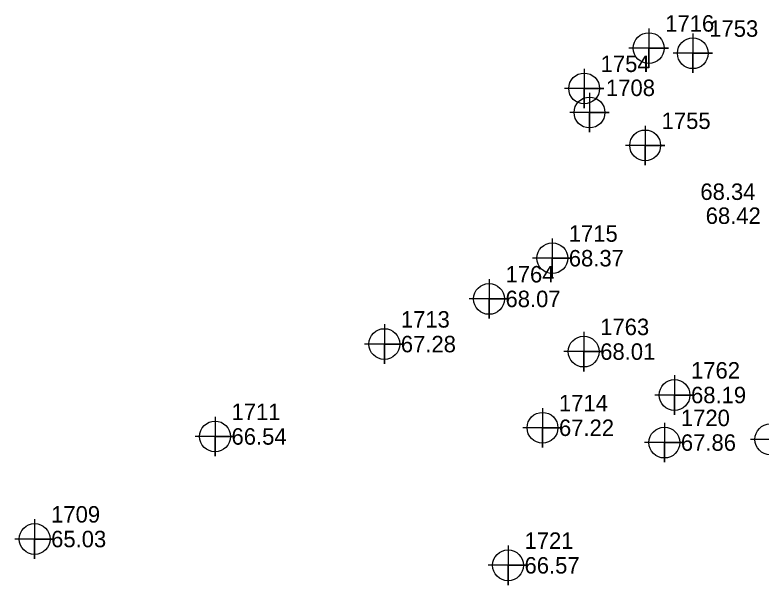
# Model space of a CAD drawing. Extents: x 2062781 to 2066835, y 358981 to 366501.
# Drawn here: x 2066253.4 to 2066366.7, y 366155.4 to 366242 of the extents above; entities that cross this region are included whole.
import ezdxf

# ---------------------------------------------------------------- set-up
doc = ezdxf.new("R2010")
doc.units = 0
for name, color, linetype in [('Exist DTM Regular Point CELL', 7, 'Continuous'), ('Exist DTM Regular Point Cogo Elevation', 7, 'Continuous'), ('Exist DTM Regular Point Cogo Number', 7, 'Continuous')]:
    doc.layers.add(name, color=color, linetype=linetype)

msp = doc.modelspace()

# ---------------------------------------------------------------- linework, layer by layer
at = {"layer": 'Exist DTM Regular Point CELL'}
for points in [[(2066349.68, 366239.93), (2066349.68, 366233.93), (2066349.68, 366236.93), (2066352.68, 366236.93), (2066346.68, 366236.93)], [(2066356.37, 366239.15), (2066356.37, 366233.15), (2066356.37, 366236.15), (2066359.37, 366236.15), (2066353.37, 366236.15)], [(2066339.88, 366233.8), (2066339.88, 366227.8), (2066339.88, 366230.8), (2066342.88, 366230.8), (2066336.88, 366230.8)], [(2066340.69, 366230.15), (2066340.69, 366224.15), (2066340.69, 366227.15), (2066343.69, 366227.15), (2066337.69, 366227.15)], [(2066349.14, 366225.15), (2066349.14, 366219.15), (2066349.14, 366222.15), (2066352.14, 366222.15), (2066346.14, 366222.15)], [(2066335.04, 366208.02), (2066335.04, 366202.02), (2066335.04, 366205.02), (2066338.04, 366205.02), (2066332.04, 366205.02)], [(2066325.43, 366201.84), (2066325.43, 366195.84), (2066325.43, 366198.84), (2066328.43, 366198.84), (2066322.43, 366198.84)], [(2066309.54, 366194.98), (2066309.54, 366188.98), (2066309.54, 366191.98), (2066312.54, 366191.98), (2066306.54, 366191.98)], [(2066339.81, 366193.84), (2066339.81, 366187.84), (2066339.81, 366190.84), (2066342.81, 366190.84), (2066336.81, 366190.84)], [(2066353.6, 366187.24), (2066353.6, 366181.24), (2066353.6, 366184.24), (2066356.6, 366184.24), (2066350.6, 366184.24)], [(2066333.55, 366182.27), (2066333.55, 366176.27), (2066333.55, 366179.27), (2066336.55, 366179.27), (2066330.55, 366179.27)], [(2066283.83, 366180.95), (2066283.83, 366174.95), (2066283.83, 366177.95), (2066286.83, 366177.95), (2066280.83, 366177.95)], [(2066352.06, 366180.02), (2066352.06, 366174.02), (2066352.06, 366177.02), (2066355.06, 366177.02), (2066349.06, 366177.02)], [(2066368.13, 366180.51), (2066368.13, 366174.51), (2066368.13, 366177.51), (2066371.13, 366177.51), (2066365.13, 366177.51)], [(2066256.44, 366165.37), (2066256.44, 366159.37), (2066256.44, 366162.37), (2066259.44, 366162.37), (2066253.44, 366162.37)], [(2066328.32, 366161.38), (2066328.32, 366155.38), (2066328.32, 366158.38), (2066331.32, 366158.38), (2066325.32, 366158.38)]]:
    msp.add_lwpolyline(points, dxfattribs=at)
for centre in [(2066349.68, 366236.93), (2066356.37, 366236.15), (2066339.88, 366230.8), (2066340.69, 366227.15), (2066349.14, 366222.15), (2066335.04, 366205.02), (2066325.43, 366198.84), (2066309.54, 366191.98), (2066339.81, 366190.84), (2066353.6, 366184.24), (2066333.55, 366179.27), (2066283.83, 366177.95), (2066352.06, 366177.02), (2066368.13, 366177.51), (2066256.44, 366162.37), (2066328.32, 366158.38)]:
    msp.add_circle(centre, 2.34, dxfattribs=at)

# ---------------------------------------------------------------- texts
at = {"layer": 'Exist DTM Regular Point Cogo Elevation'}
for s, p in [('68.34', (2066357.52, 366213.87)), ('68.42', (2066358.33, 366210.23)), ('68.37', (2066337.54, 366203.77)), ('68.07', (2066327.93, 366197.59)), ('67.28', (2066312.04, 366190.73)), ('68.01', (2066342.31, 366189.59)), ('68.19', (2066356.1, 366182.99)), ('67.22', (2066336.05, 366178.02)), ('66.54', (2066286.33, 366176.7)), ('67.86', (2066354.56, 366175.77)), ('65.03', (2066258.94, 366161.12)), ('66.57', (2066330.82, 366157.13))]:
    msp.add_text(s, height=2.5, dxfattribs=at).set_placement(p)
at = {"layer": 'Exist DTM Regular Point Cogo Number'}
for s, p in [('1716', (2066352.18, 366239.43)), ('1753', (2066358.87, 366238.65)), ('1754', (2066342.38, 366233.3)), ('1708', (2066343.19, 366229.65)), ('1755', (2066351.64, 366224.65)), ('1715', (2066337.54, 366207.52)), ('1764', (2066327.93, 366201.34)), ('1713', (2066312.04, 366194.48)), ('1763', (2066342.31, 366193.34)), ('1762', (2066356.1, 366186.74)), ('1714', (2066336.05, 366181.77)), ('1711', (2066286.33, 366180.45)), ('1720', (2066354.56, 366179.52)), ('1709', (2066258.94, 366164.87)), ('1721', (2066330.82, 366160.88))]:
    msp.add_text(s, height=2.5, dxfattribs=at).set_placement(p)

doc.saveas('drawing.dxf')
